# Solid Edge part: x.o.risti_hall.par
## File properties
Author: Romil
Template: iso part.par
Last saved by: Romil
Revision: 37
Application: Solid Edge
Accuracy: 0.990
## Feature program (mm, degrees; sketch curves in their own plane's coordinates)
sketch used by "unnamed Protrusion 1" plane through (0, 0, 0) normal (0, -1, 0) x-axis (1, 0, 0)
extrude "unnamed Protrusion 1" add finite 7.8 symmetric
sketch used by "ExtrudedProtrusion_4" plane through (0, 0, 0) normal (1, 0, 0) x-axis (0, 1, 0)
extrude "ExtrudedProtrusion_4" add finite 7.8 symmetric
sketch for "unnamed RevolvedCutout 1" plane through (0, 0, 0) normal (0, -1, 0) x-axis (1, 0, 0)
revolve "unnamed RevolvedCutout 1" cut finite 360 deg
sketch for "unnamed Protrusion 2" plane through (0, 0, 0) normal (0, 0, 1) x-axis (1, 0, 0)
  line (-3.6217, 3.6) -> (-2.7879, 3.6)
  line (-2.7879, 3.6) -> (-2.7879, -3.6)
  line (-2.7879, -3.6) -> (-3.6217, -3.6)
  line (-3.6217, -3.6) -> (-3.6217, 1.953)
  line (-3.6217, 3.6) -> (-3.6217, 1.953)
extrude "unnamed Protrusion 2" add to key point along +normal
mirror "unnamed Mirror 1" of "unnamed Protrusion 2" about plane through (0, 0, 0) normal (1, 0, 0)
extrude "unnamed Protrusion 3" add finite 7.9783
sketch for "unnamed Protrusion 4" plane through (0, 0, 0) normal (0, 0, 1) x-axis (1, 0, 0)
  line (3.35, -0.6) -> (-3.35, -0.6)
  line (-3.35, -0.6) -> (-3.35, 0.6)
  line (-3.35, 0.6) -> (3.35, 0.6)
  line (3.35, 0.6) -> (3.35, -0.6)
extrude "unnamed Protrusion 4" add to key point along +normal
sketch for "unnamed Cutout 1" plane through (0, -3.9, 7.9783) normal (0, -1, 0) x-axis (1, 0, 0)
extrude "unnamed Cutout 1" cut finite 0.9 along -normal
mirror "unnamed Mirror 2" of "unnamed Cutout 1" about plane through (0, 0, 0) normal (0, -1, 0)
extrude "unnamed Cutout 2" cut finite 0.9
sketch for "ExtrudedCutout_17" plane through (0, 0, 0) normal (0, -1, 0) x-axis (1, 0, 0)
extrude "ExtrudedCutout_17" cut finite 184.7238 symmetric
sketch for "ExtrudedCutout_21" plane through (0, 0, 0) normal (1, 0, 0) x-axis (0, 1, 0)
  arc centre (0, 0) radius 2.35 from (-2.181, -0.875) to (-2.181, 0.875) cw
  arc centre (0, 0) radius 2.35 from (-0.875, 2.181) to (0.875, 2.181) cw
  arc centre (0, 0) radius 2.35 from (2.181, 0.875) to (2.181, -0.875) cw
extrude "ExtrudedCutout_21" cut finite 60.1924 symmetric
fillet "Round_8" radius 0.2
sketch for "ExtrudedCutout_22" plane through (0, 0, 0) normal (0, -1, 0) x-axis (1, 0, 0)
  line (2.7, 0.6) -> (-2.7, 0.6)
  line (-2.7, 0.6) -> (-2.7, -0.6)
  line (-2.7, -0.6) -> (2.7, -0.6)
  line (2.7, -0.6) -> (2.7, 0.6)
extrude "ExtrudedCutout_22" cut finite 85.6625 symmetric
fillet "Round_9" radius 0.4
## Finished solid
Body 1: solid body, 81 faces, 198 edges, 116 vertices.
  Faces by surface: plane 36, cylinder 35, blend 8, torus 2
  Edges by curve: line 100, circle 58, intersection 24, ellipse 16
Bounding box of the edges (mm; curved faces can reach further): 7.800 x 7.800 x 15.200, from (-3.9, -3.9, -3.6) to (3.9, 3.9, 11.6).
Cylindrical faces by radius (mm): R0.1 x4, R0.2 x2, R0.4 x16, R2.35 x4, R2.4 x1, R3.0587 x3, R3.1 x2, R3.6 x2, R3.6217 x1
Toroidal faces (ring radius, tube radius in mm): R3.3 r0.3 x2
Planar faces by outward normal: +x 5, +y 7, +z 4, -x 5, -y 7, -z 8
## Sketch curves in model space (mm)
line (2.7, 0, -0.6) -> (2.7, 0, 0.6)
line (2.7, 0, 0.6) -> (-2.7, 0, 0.6)
line (-2.7, 0, 0.6) -> (-2.7, 0, -0.6)
line (-2.7, 0, -0.6) -> (2.7, 0, -0.6)
line (-3.35, -0.6, 0) -> (-3.35, 0.6, 0)
line (-3.35, 0.6, 0) -> (3.35, 0.6, 0)
line (3.35, 0.6, 0) -> (3.35, -0.6, 0)
line (3.35, -0.6, 0) -> (-3.35, -0.6, 0)
line (-4.4651, 0, 0) -> (5.0671, 0, 0)
line (2.7, 0, 3.0587) -> (2.7, 0, 3.3)
arc centre (3, 0, 3.3) radius 0.3 from (2.7, 0, 3.3) through (2.7941, 0, 3.5182) to (3, 0, 3.6)
line (3, 0, 3.6) -> (3.9, 0, 3.6)
line (3.9, 0, 3.6) -> (3.9, 0, 4.041)
line (3.9, 0, 4.041) -> (-3.9, 0, 4.041)
line (-3.9, 0, 4.041) -> (-3.9, 0, 3.6)
line (-3.9, 0, 3.6) -> (-3, 0, 3.6)
arc centre (-3, 0, 3.3) radius 0.3 from (-2.7, 0, 3.3) through (-2.7941, 0, 3.5182) to (-3, 0, 3.6)
line (-2.7, 0, 3.3) -> (-2.7, 0, 3.0587)
line (-2.7, 0, 3.0587) -> (2.7, 0, 3.0587)
circle centre (0, 0, 7.9783) radius 2.4
circle centre (0, 0, 7.9783) radius 3.6217
line (-3.6217, -3.6, 0) -> (-3.6217, 1.953, 0)
line (-2.7879, -3.6, 0) -> (-3.6217, -3.6, 0)
line (-2.7879, 3.6, 0) -> (-2.7879, -3.6, 0)
line (-3.6217, 3.6, 0) -> (-2.7879, 3.6, 0)
line (-3.6217, 3.6, 0) -> (-3.6217, 1.953, 0)
circle centre (0, -3.9, 7.9783) radius 3.1
circle centre (0, 0, 0) radius 3.6
circle centre (0, 0, 8) radius 3.6
arc centre (0, -0.975, -0.975) radius 0.1 from (0, -0.975, -0.875) through (0, -0.9023, -0.9064) to (0, -0.875, -0.975)
line (0, -0.875, -0.975) -> (0, -0.875, -2.181)
arc centre (0, 0, 0) radius 2.35 from (0, 0.875, -2.181) through (0, 0, -2.35) to (0, -0.875, -2.181)
line (0, 0.875, -2.181) -> (0, 0.875, -0.975)
arc centre (0, 0.975, -0.975) radius 0.1 from (0, 0.875, -0.975) through (0, 0.9064, -0.9023) to (0, 0.975, -0.875)
line (0, 0.975, -0.875) -> (0, 2.181, -0.875)
arc centre (0, 0, 0) radius 2.35 from (0, 2.181, 0.875) through (0, 2.35, 0) to (0, 2.181, -0.875)
line (0, 2.181, 0.875) -> (0, 0.975, 0.875)
arc centre (0, 0.975, 0.975) radius 0.1 from (0, 0.975, 0.875) through (0, 0.9023, 0.9064) to (0, 0.875, 0.975)
line (0, 0.875, 0.975) -> (0, 0.875, 2.181)
arc centre (0, 0, 0) radius 2.35 from (0, -0.875, 2.181) through (0, 0, 2.35) to (0, 0.875, 2.181)
line (0, -0.875, 2.181) -> (0, -0.875, 0.975)
arc centre (0, -0.975, 0.975) radius 0.1 from (0, -0.875, 0.975) through (0, -0.9064, 0.9023) to (0, -0.975, 0.875)
line (0, -0.975, 0.875) -> (0, -2.181, 0.875)
arc centre (0, 0, 0) radius 2.35 from (0, -2.181, -0.875) through (0, -2.35, 0) to (0, -2.181, 0.875)
line (0, -2.181, -0.875) -> (0, -0.975, -0.875)
line (0, 3.6, 0) -> (0, 3.9, 11.6)
arc centre (0, 0, 0) radius 3.6 from (0, 3.6, 0) through (0, -0.1067, -3.5984) to (0, -3.6, 0)
line (0, -3.6, 0) -> (0, -3.9, 11.6)
line (0, 0, 11.6) -> (0, -3.9, 11.6)
line (0, 0, 11.6) -> (0, 3.9, 11.6)
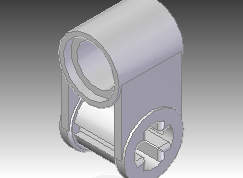
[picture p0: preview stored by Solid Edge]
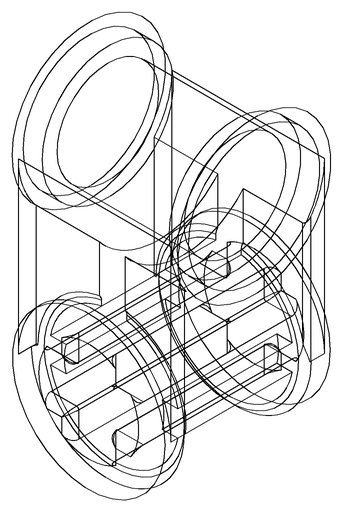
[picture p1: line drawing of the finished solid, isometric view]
